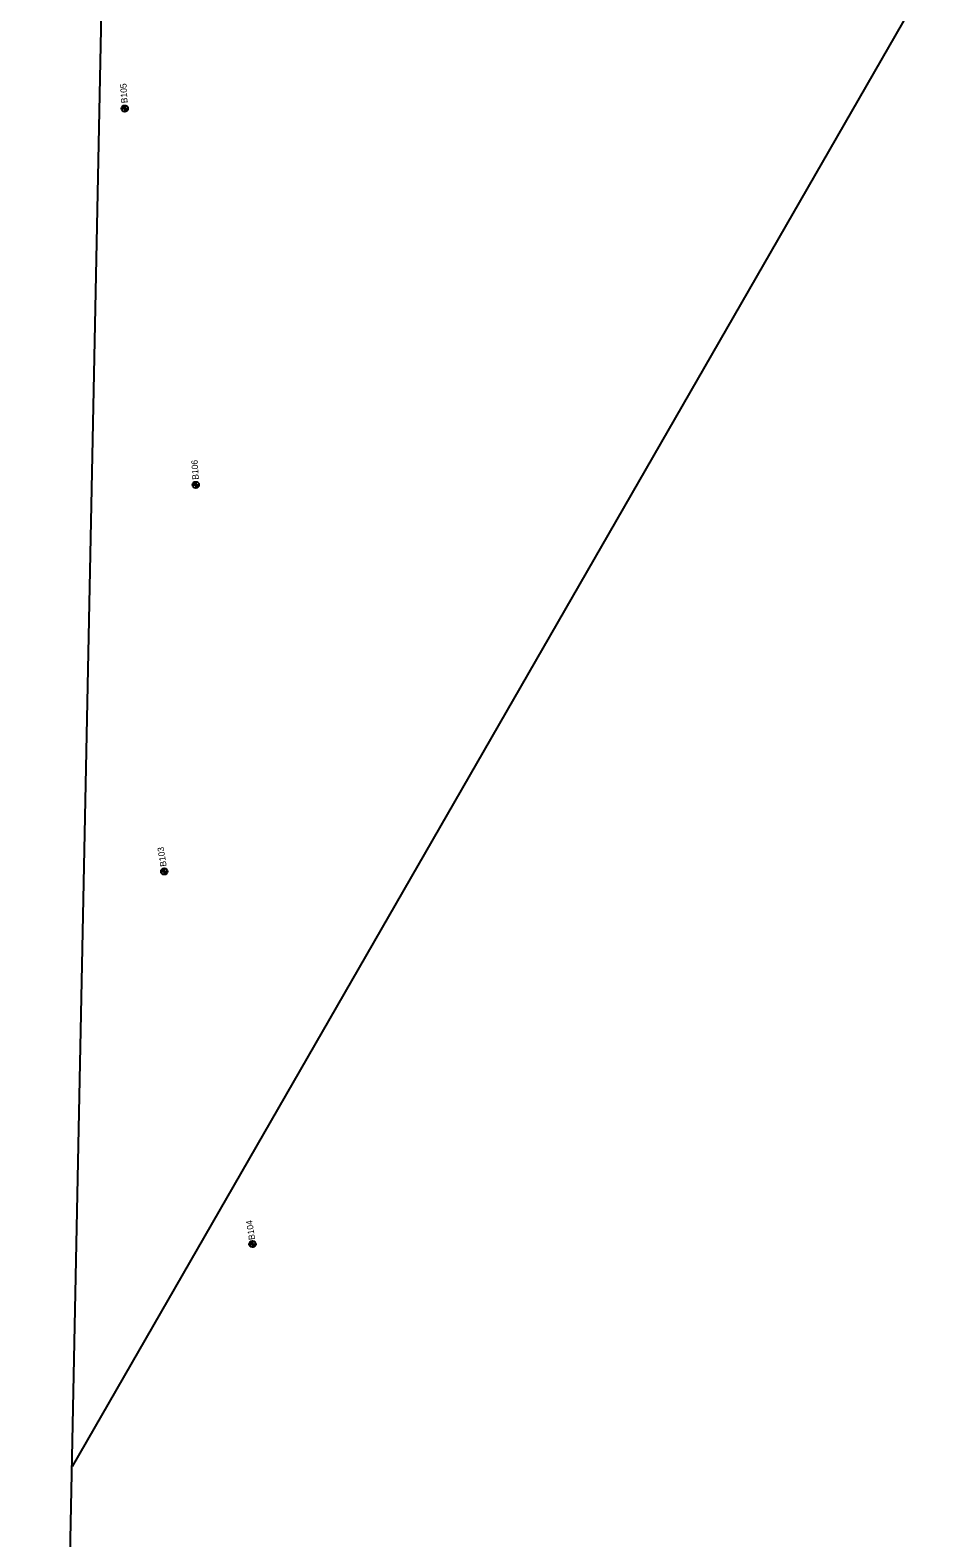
# Model space of a CAD drawing. Extents: x 345549 to 379569, y 127949 to 230467.
# Drawn here: x 355372 to 356786, y 184347 to 186721 of the extents above; entities that cross this region are included whole.
import ezdxf

# ---------------------------------------------------------------- set-up
doc = ezdxf.new("R2010")
doc.units = 0
for name, color, linetype in [('E_RDWY', 7, 'Continuous'), ('E_SOIL_BORE1 [KAPUR_CADDS_LEVELS]', 7, 'Continuous'), ('E_SOIL_BORE2 [KAPUR_CADDS_LEVELS]', 7, 'Continuous'), ('P_MARK', 7, 'Continuous')]:
    doc.layers.add(name, color=color, linetype=linetype)

msp = doc.modelspace()

# ---------------------------------------------------------------- linework, layer by layer
at = {"layer": 'E_RDWY'}
for p, q in [((355372.5, 181177.5), (356094.5, 217027.6)), ((358200.3, 189259.9), (355438.6, 184458.8))]:
    msp.add_line(p, q, dxfattribs=at)
at = {"layer": 'P_MARK'}
for p, q in [((355516.5, 186597.6), (355526.5, 186597.6)), ((355521.5, 186602.6), (355521.5, 186592.6)), ((355628.3, 186004.9), (355638.3, 186004.9)), ((355633.3, 186009.9), (355633.3, 185999.9)), ((355578.7, 185396.1), (355588.7, 185396.1)), ((355583.7, 185401.1), (355583.7, 185391.1)), ((355717.7, 184809.3), (355727.7, 184809.3)), ((355722.7, 184814.3), (355722.7, 184804.3))]:
    msp.add_line(p, q, dxfattribs=at)
for centre in [(355521.5, 186597.6), (355633.3, 186004.9), (355583.7, 185396.1), (355722.7, 184809.3)]:
    msp.add_circle(centre, 5, dxfattribs=at)
for centre, radius, start, end in [((355521.5, 186597.6), 4.5, 89.9869, 179.9869), ((355521.5, 186597.6), 4, 89.9869, 179.9869), ((355521.5, 186597.6), 3.5, 89.9869, 179.9869), ((355521.5, 186597.6), 3, 89.9869, 179.9869), ((355521.5, 186597.6), 2.5, 89.9869, 179.9869), ((355521.5, 186597.6), 2, 89.9869, 179.9869), ((355521.5, 186597.6), 1.5, 89.9869, 179.9869), ((355521.5, 186597.6), 1, 89.9869, 179.9869), ((355521.5, 186597.6), 0.5, 89.9869, 179.9869), ((355521.5, 186597.6), 4.5, 269.9869, 359.9869), ((355521.5, 186597.6), 4, 269.9869, 359.9869), ((355521.5, 186597.6), 3.5, 269.9869, 359.9869), ((355521.5, 186597.6), 3, 269.9869, 359.9869), ((355521.5, 186597.6), 2.5, 269.9869, 359.9869), ((355521.5, 186597.6), 2, 269.9869, 359.9869), ((355521.5, 186597.6), 1.5, 269.9869, 359.9869), ((355521.5, 186597.6), 1, 269.9869, 359.9869), ((355521.5, 186597.6), 0.5, 269.9869, 359.9869), ((355633.3, 186004.9), 4.5, 89.9869, 179.9869), ((355633.3, 186004.9), 4, 89.9869, 179.9869), ((355633.3, 186004.9), 3.5, 89.9869, 179.9869), ((355633.3, 186004.9), 3, 89.9869, 179.9869), ((355633.3, 186004.9), 2.5, 89.9869, 179.9869), ((355633.3, 186004.9), 2, 89.9869, 179.9869), ((355633.3, 186004.9), 1.5, 89.9869, 179.9869), ((355633.3, 186004.9), 1, 89.9869, 179.9869), ((355633.3, 186004.9), 0.5, 89.9869, 179.9869), ((355633.3, 186004.9), 4.5, 269.9869, 359.9869), ((355633.3, 186004.9), 4, 269.9869, 359.9869), ((355633.3, 186004.9), 3.5, 269.9869, 359.9869), ((355633.3, 186004.9), 3, 269.9869, 359.9869), ((355633.3, 186004.9), 2.5, 269.9869, 359.9869), ((355633.3, 186004.9), 2, 269.9869, 359.9869), ((355633.3, 186004.9), 1.5, 269.9869, 359.9869), ((355633.3, 186004.9), 1, 269.9869, 359.9869), ((355633.3, 186004.9), 0.5, 269.9869, 359.9869), ((355583.7, 185396.1), 4.5, 89.9869, 179.9869), ((355583.7, 185396.1), 4, 89.9869, 179.9869), ((355583.7, 185396.1), 3.5, 89.9869, 179.9869), ((355583.7, 185396.1), 3, 89.9869, 179.9869), ((355583.7, 185396.1), 2.5, 89.9869, 179.9869), ((355583.7, 185396.1), 2, 89.9869, 179.9869), ((355583.7, 185396.1), 1.5, 89.9869, 179.9869), ((355583.7, 185396.1), 1, 89.9869, 179.9869), ((355583.7, 185396.1), 0.5, 89.9869, 179.9869), ((355583.7, 185396.1), 4.5, 269.9869, 359.9869), ((355583.7, 185396.1), 4, 269.9869, 359.9869), ((355583.7, 185396.1), 3.5, 269.9869, 359.9869), ((355583.7, 185396.1), 3, 269.9869, 359.9869), ((355583.7, 185396.1), 2.5, 269.9869, 359.9869), ((355583.7, 185396.1), 2, 269.9869, 359.9869), ((355583.7, 185396.1), 1.5, 269.9869, 359.9869), ((355583.7, 185396.1), 1, 269.9869, 359.9869), ((355583.7, 185396.1), 0.5, 269.9869, 359.9869), ((355722.7, 184809.3), 4.5, 89.9869, 179.9869), ((355722.7, 184809.3), 4, 89.9869, 179.9869), ((355722.7, 184809.3), 3.5, 89.9869, 179.9869), ((355722.7, 184809.3), 3, 89.9869, 179.9869), ((355722.7, 184809.3), 2.5, 89.9869, 179.9869), ((355722.7, 184809.3), 2, 89.9869, 179.9869), ((355722.7, 184809.3), 1.5, 89.9869, 179.9869), ((355722.7, 184809.3), 1, 89.9869, 179.9869), ((355722.7, 184809.3), 0.5, 89.9869, 179.9869), ((355722.7, 184809.3), 4.5, 269.9869, 359.9869), ((355722.7, 184809.3), 4, 269.9869, 359.9869), ((355722.7, 184809.3), 3.5, 269.9869, 359.9869), ((355722.7, 184809.3), 3, 269.9869, 359.9869), ((355722.7, 184809.3), 2.5, 269.9869, 359.9869), ((355722.7, 184809.3), 2, 269.9869, 359.9869), ((355722.7, 184809.3), 1.5, 269.9869, 359.9869), ((355722.7, 184809.3), 1, 269.9869, 359.9869), ((355722.7, 184809.3), 0.5, 269.9869, 359.9869)]:
    msp.add_arc(centre, radius, start, end, dxfattribs=at)

# ---------------------------------------------------------------- texts
at = {"layer": 'E_SOIL_BORE1 [KAPUR_CADDS_LEVELS]'}
for s, rotation, p in [('B105', 93.5868, (355526, 186606.3)), ('B104', 98.957, (355727, 184816.6))]:
    msp.add_text(s, height=10, rotation=rotation, dxfattribs=at).set_placement(p)
at = {"layer": 'E_SOIL_BORE2 [KAPUR_CADDS_LEVELS]'}
for s, rotation, p in [('B106', 93.5868, (355638.1, 186013.3)), ('B103', 98.957, (355587.5, 185404.5))]:
    msp.add_text(s, height=10, rotation=rotation, dxfattribs=at).set_placement(p)

doc.saveas('drawing.dxf')
